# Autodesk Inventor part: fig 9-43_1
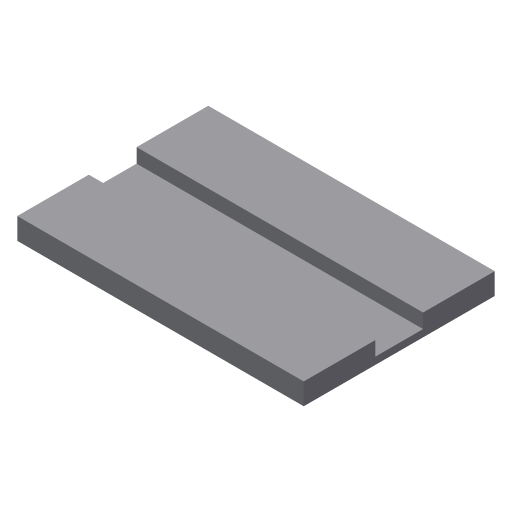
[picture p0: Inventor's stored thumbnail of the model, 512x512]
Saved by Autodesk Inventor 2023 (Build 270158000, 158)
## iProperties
Created: 2013-03
Part Number: fig 9-43_1
Material: Generic
Document SubType Name: Modeling
Designer: CADCIM
Density: 1 g/cm^3
Appearance: Default
Author: CADCIM
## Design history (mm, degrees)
sketch "Sketch1"
  geometry: L1 (-12.966, 10)-(17.034, 10); L2 (17.034, 10)-(17.034, -10); L3 (17.034, -10)-(-12.966, -10); L4 (-12.966, -10)-(-12.966, 10); 1 further point
  constraints: 8 end point, 2 parallel, 1 horizontal, 1 perpendicular
  dimensions: "d0" = 30 distance of L1.start L1.end; "d2" = 20 distance of L1.end L2.end
extrude "Extrusion1" new body sketch "Sketch1" distance "d3" = 2.25; taper "d4" = 0 deg
sketch "Sketch2"
  geometry: L1 (-12.966, 10)-(-12.966, -10) reference; L2 (-12.966, 2.498)-(87.034, 2.498); L3 (87.034, 2.498)-(87.034, -2.502); L4 (87.034, -2.502)-(-12.966, -2.502); L5 (-12.966, -2.502)-(-12.966, 2.498); 1 further point
  constraints: 8 end point, 2 parallel, 1 horizontal, 1 perpendicular, 1 point on line
  dimensions: "d5" = 5 distance of L2.end L3.end; "d7" = 100 distance of L2.start L2.end
extrude "Extrusion2" cut sketch "Sketch2" distance "d8" = 1.5; taper "d9" = 0 deg
body "Solid1"
